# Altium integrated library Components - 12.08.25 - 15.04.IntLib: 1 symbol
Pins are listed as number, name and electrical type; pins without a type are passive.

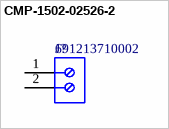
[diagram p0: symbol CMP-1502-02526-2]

## CMP-1502-02526-2
designator J?, comment 691213710002
NexarPartId: 8917718; Number of Contacts: 2; Current Rating: 10A; Stripping Length: -7mm; Wire Gauge (Max): 26AWG; Plating: Brass, Steel; Wire Gauge (Min): 16AWG; Voltage: 300V; Number of Levels: 1; Pitch: 5.0038mm
footprint 691213710002 (5,00mm - modular - green - Horizontal entry with rising cage clamp -  10,0mm height - 02p)
pins: 1, 2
